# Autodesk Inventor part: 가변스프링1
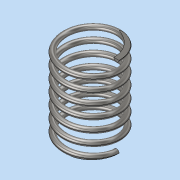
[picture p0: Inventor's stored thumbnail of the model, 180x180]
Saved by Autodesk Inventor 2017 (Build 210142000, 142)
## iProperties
Part Number: 가변스프링1
Material: 스테인레스 스틸
Document SubType Name: Modeling
Designer: MRC
Density: 8 g/cm^3
Appearance: 반연마
Mass: 10.9602 g
Surface Area: 27.6886 cm^2
Volume: 1.37003 cm^3
Author: MRC
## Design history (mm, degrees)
sketch "스케치1"
  geometry: L1 (0, 0)-(10, 0); L2 (10, 0)-(10, 30.358); L3 (10, 30.358)-(0, 30.358); L4 (0, 30.358)-(0, 0); C1 r 1 at (10, 0)
  constraints: 8 end point, 2 parallel, 1 centre point, 1 coincident, 1 horizontal, 1 perpendicular
  dimensions: "d0" = 20 diameter of L2 L4; "d1" = 30.35829 distance of L1.end L2.end (derived); "d2" = 2 diameter of C1
feature "코일1" sketch "스케치1" pitch "d3" = 10; turns "d5" = 7; dims "d4" = 30.35829 (= d1), "d6" = 0, angle "d7" = 90 deg, angle "d8" = 90 deg, "d9" = 0, "d10" = 0
sketch "스케치2"
  geometry: L1 (-15, 30.358)-(15, 30.358); L2 (15, 30.358)-(15, 0); L3 (15, 0)-(-15, 0); L4 (-15, 0)-(-15, 30.358); L5 (0, 30.358)-(0, 0) reference; 2 further points
  constraints: 8 end point, 2 midpoint, 2 parallel, 1 coincident, 1 horizontal, 1 perpendicular
  dimensions: "d11" = 30 distance of L1.start L1.end
extrude "돌출1" sketch "스케치2" stored distance "d12" = 0; taper "d13" = 0 deg
node "솔리드1"
